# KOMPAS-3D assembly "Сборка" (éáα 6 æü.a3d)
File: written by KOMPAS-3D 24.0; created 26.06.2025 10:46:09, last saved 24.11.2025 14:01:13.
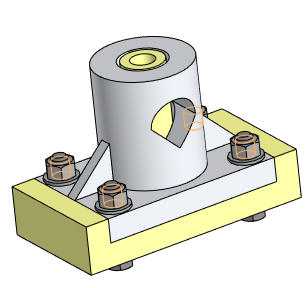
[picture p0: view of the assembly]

Document properties: Автор: Helen; Полное имя файла: C:\Для ноута\Инженерная графика\ППЭ 2025-2026\Варианты 1-38\Вариант 6 СБ\Решение 6\Вар 6 СБ\Вар 6 СБ.a3d

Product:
- Component [detail]: Сборка  | qty 4  | Масса: 0.008612; Автор: PC321; source file: ..\..\..\Вариант 5 СБ\Вар 5 СБ\Шайба 14.m3d
- Component [detail]: Сборка  | qty 4  | Масса: 0.02533; Автор: PC321; source file: ..\..\..\Вариант 5 СБ\Вар 5 СБ\Гайка М14.m3d
- Component [detail]: Болт М14x60 ГОСТ 15591-70  | qty 4  | Масса: 0.091885; source file: ..\..\..\Вариант 5 СБ\Вар 5 СБ\Болт М14x60 ГОСТ 15591-70.m3d
- Component [detail]: Деталь  | qty 1  | Автор: Helen; source file: Деталь.m3d
- Component [detail]: Основание  | designation Вариант 6  | qty 1  | Масса: 4.013273; Автор: Helen; source file: Основание вар 6.m3d
- Component [detail]: Nodes  | qty 1  | Масса: 4.48808; Автор: Helen; source file: Корпус вар 6.m3d
- Part/product: Сборка
    Масса: 9.00466

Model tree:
1. Массив по сетке:1  (with: Операция без истории:1, Элемент выдавливания:4, Элемент выдавливания:1)  (4 pattern instances)
     Шаг 1 = 120; Угол раствора = 90; Шаг 2 = 70; Ориентация = 2

Referenced files in C:\Для ноута\Инженерная графика\ППЭ 2025-2026\Варианты 1-38\Вариант 6 СБ\Решение 6\Вар 6 СБ\: Основание вар 6.m3d, Деталь.m3d, Корпус вар 6.m3d
Referenced files in C:\Для ноута\Инженерная графика\ППЭ 2025-2026\Варианты 1-38\Вариант 5 СБ\Вар 5 СБ\: Шайба 14.m3d, Гайка М14.m3d, Болт М14x60 ГОСТ 15591-70.m3d
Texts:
  Сборка (1)
  Болт М14x60 ГОСТ 15591-70 (1)
  Вариант 6 Основание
